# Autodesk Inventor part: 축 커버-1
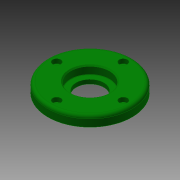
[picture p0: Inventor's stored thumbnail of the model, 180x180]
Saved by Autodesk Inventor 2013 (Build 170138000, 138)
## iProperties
Created: 2015-10
Part Number: 축 커버-1
Document SubType Name: Modeling
Designer: mdu
Density: 7.86 g/cm^3
Material: 강철, 연강
Mass: 366.754 g
Surface Area: 144.304 cm^2
Volume: 46.6609 cm^3
Author: mdu
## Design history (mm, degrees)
sketch "스케치1"
  geometry: C1 r 41 at (0, 0); C2 r 26 at (0, 0) reference; 1 further point
  constraints: 1 centre point, 1 coincident
  dimensions: "d31" = 82 diameter of C1
  node "참조2"
extrude "돌출1" new body sketch "스케치1" distance "d0" = 10; taper "d1" = 0 deg
extrude "돌출2" join sketch "스케치1" distance "d2" = 5; taper "d3" = 0 deg
hole "구멍1" diameter "d6" = 27; stored, may be unused: countersink angle "d10" = 90 deg, drill point angle "d12" = 118 deg; dims "d4" = 10, "d5" = 10, "d7" = 6, "d8" = 38, "d9" = 8, "d11" = 8
sketch "스케치2"
  geometry: C1 r 20 at (0, 0); 1 further point
  constraints: 1 centre point, 1 coincident
  dimensions: "d13" = 40 diameter of C1
extrude "돌출3" cut sketch "스케치2" distance "d14" = 3; taper "d15" = 0 deg
sketch "스케치3"
  geometry: C1 r 1.621 at (0, 32.5) reference; 1 further point
hole "구멍2" sketch "스케치3" at (0, 32.5) diameter "d16" = 4.5; stored, may be unused: countersink angle "d20" = 90 deg, drill point angle "d22" = 118 deg; dims "d17" = 6, "d18" = 8, "d19" = 4.4, "d21" = 8
fillet "모깎기1" dims "d26" = 3, "d27" = 0.3
chamfer "모따기1" distance "d28" = 1; stored, may be unused: second distance "d29" = 2, angle "d30" = 45 deg
node "솔리드1"
pattern_circular "원형 패턴1" dims angle "d24" = 360 deg
node "참조3"
